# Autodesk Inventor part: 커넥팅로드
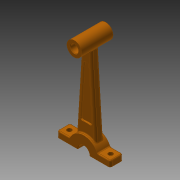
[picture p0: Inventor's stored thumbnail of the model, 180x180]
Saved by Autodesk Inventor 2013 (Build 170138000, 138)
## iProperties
Created: 2016-11
Part Number: 커넥팅로드
Material: 알루미늄 6061
Document SubType Name: Modeling
Designer: mduedu
Density: 2.71 g/cm^3
Mass: 44.5487 g
Surface Area: 86.7069 cm^2
Volume: 16.4386 cm^3
Author: mduedu
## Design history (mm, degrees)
sketch "스케치1" dims "d0" = 30, "d3" = 15
  geometry: L1 (0, 0)-(0, 96); L2 (-5, 90.41)-(-10, 11.18); L3 (5, 90.41)-(10, 11.18); C1 r 6 at (0, 0); C2 r 4 at (0, 96); 3 further points
  constraints: 6 end point, 4 coincident, 2 centre point, 2 symmetric about line, 1 vertical, 6 other
  dimensions: "d1" = 12 diameter of C1; "d2" = 8 diameter of C2; "d4" = 96 distance of L1.start L1.end; "d6" = 10 distance from line of L1 L2.end; "d7" = 5 distance from line of L1 L2.start
extrude "돌출1" new body sketch "스케치1" stored distance "d8" = 13; taper "d9" = 0 deg
extrude "돌출2" join sketch "스케치1" stored distance "d10" = 32; taper "d11" = 0 deg
sketch "스케치2"
  geometry: L1 (5, 90.41)-(10, 11.18) reference; L2 (-5, 90.41)-(-10, 11.18) reference; A1 r 7.5 centre (0, 96) between (5, 90.41) and (-5, 90.41) reference; A2 r 15 centre (0, 0) between (10, 11.18) and (-10, 11.18) reference
extrude "돌출3" join sketch "스케치2" stored distance "d12" = 8; taper "d13" = 0 deg
sketch "스케치3"
  geometry: L1 (-2.732, 78.715)-(-6.171, 24.226); L2 (2.732, 78.715)-(6.171, 24.226); L3 (0, 78.5)-(0, 25); A1 r 17.5 centre (0, 96) between (-2.732, 78.715) and (2.732, 78.715); A2 r 25 centre (0, 0) between (6.171, 24.226) and (-6.171, 24.226); 9 further points; 2 other entities
  constraints: 6 end point, 6 point on circle, 2 centre point, 1 symmetric about line, 1 vertical alignment, 6 other
  dimensions: "d18" = 10 dimension on A1; "d19" = 10 dimension on A2; "d20" = 3 dimension on L1
extrude "돌출4" cut sketch "스케치3" distance "d21" = 2; taper "d22" = 0 deg
fillet "모깎기1" dims "d23" = 2
fillet "모깎기2" dims "d24" = 2
fillet "모깎기3" dims "d25" = 1
chamfer "모따기1" distance "d26" = 0.5; stored, may be unused: second distance "d27" = 2, angle "d28" = 45 deg
sketch "스케치4"
  geometry: L1 (-27, -6)-(-13.748, -6); L2 (27, -6)-(27, 6); L3 (27, 6)-(13.748, 6); L4 (-27, 6)-(-27, -6); L5 (-27, -6)-(27, 6); L6 (27, -6)-(-27, 6); L7 (-13.748, 6)-(-27, 6); L8 (13.748, 6)-(-13.748, 6); L9 (13.748, -6)-(27, -6); L10 (-13.748, -6)-(13.748, -6); A1 r 15 centre (0, 0) between (-13.748, 6) and (13.748, 6) reference; 1 further point
  constraints: 20 end point, 10 parallel, 4 point on circle, 3 horizontal, 3 perpendicular, 2 midpoint
  dimensions: "d29" = 54 distance of L1.start L2.start; "d31" = 12 distance of L2.start L2.end
extrude "돌출5" join sketch "스케치4" stored distance "d32" = 0; taper "d33" = 0 deg
fillet "모깎기4" dims "d34" = 2
fillet "모깎기5" dims "d35" = 1
fillet "모깎기6" dims "d36" = 1
sketch "스케치5"
  geometry: L1 (1, 0)-(1, 9) reference; L2 (-18.5, 20.5)-(-33.5, 20.5) reference; L3 (-33.5, -11.5)-(-18.5, -11.5) reference; L4 (-26, 20.5)-(-26, -11.5); 3 further points
  constraints: 2 end point, 2 midpoint, 1 horizontal alignment, 1 symmetric about line
  dimensions: "d37" = 6 distance from line of point (-5, 4.5) L1
feature "분할1"
sketch "스케치7"
  geometry: 2 further points
  constraints: 2 other
hole "구멍2" sketch "스케치7" at (-47, 4.5), (-5, 4.5) diameter "d45" = 4.5; stored, may be unused: countersink angle "d49" = 90 deg, drill point angle "d51" = 0 deg; dims "d46" = 6, "d47" = 4, "d48" = 2, "d50" = 8
node "솔리드1"
mirror "대칭1"
other parameters: "d16" = 4, "d17" = 4
